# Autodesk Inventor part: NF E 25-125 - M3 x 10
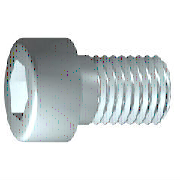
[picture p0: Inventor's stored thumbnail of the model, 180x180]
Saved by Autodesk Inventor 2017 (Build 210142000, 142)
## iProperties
Comments: To add or edit properties for Autodesk Inventor files, use iProperties.
Created: 2004-01
Part Number: NF E 25-125 - M3 x 10
Vendor: Autodesk Inc.
Document SubType Name: Modeling
Designer: Administrator
Material: Generic
Description: Cylinder Head Cap Screw
Standard: NF E 25-125
Size Designation: M3 x 10
Density: 1 g/cm^3
Appearance: Default
Alert: To add or edit properties for Autodesk Inventor files, use iProperties.
Control State: 0
Master: False
Checked Out: False
Shininess: 64.0
Length Units: 11269
Angle Units: 11279
Time Units: 11290
Mass Units: 11283
Length Display Precision: 3
Angle Display Precision: 2
Compacted: True
EGR: 1
Density: 0.0
Volumn: 0.0
Area: 0.0
PropertySet Name: Model Information
Author: Administrator
Revision Number: 8
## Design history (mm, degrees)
sketch "Sketch1"
  geometry: L1 (-0.867, 0)-(10, 0); L2 (10, 0)-(10, 1.5); L3 (10, 1.5)-(1.25, 1.5); L4 (1.25, 1.5)-(0.943, 1.5); L5 (0.943, 1.5)-(0, 1.5); L6 (0, 1.5)-(0, 2.75); L7 (0, 2.75)-(-3, 2.75); L8 (-3, 2.75)-(-3, 1.443); L9 (-3, 1.443)-(-1.7, 1.443); L10 (-1.7, 1.443)-(-0.867, 0); L11 (-4.3, 0)-(13.9, 0) reference; L12 (0, -0.275)-(0, 3.575) reference; L13 (1.25, 1.5)-(0, 1.5)
  constraints: 22 end point, 6 parallel, 2 collinear, 2 perpendicular, 1 horizontal, 1 point on line
  dimensions: "d1" = 8.75 distance from line of L3.end L2 (= GEL); "d2" = 0.30683 distance of L4.end L3.end (computed from GAL); "d3" = 3 distance between parallel lines of L8 L6 (= KOH); "d4" = 1.3 distance of L8.end L9.end (= INTI); "d5" = 60 deg angle of L10 L1; "d6" = 3 diameter of L3 L1 (= GD); "d7" = 3 diameter of L5 L1 (= BDM); "d8" = 2.88675 diameter of L9 L1 (= 1.1547 x SW); "d9" = 5.5 diameter of L7 L1 (= KOD); "d26" = 10 distance between parallel lines of L12 L2 (= NLG)
revolve "Body" sketch "Sketch1" stored, may be unused: angle "d10" = 90 deg
sketch "Sketch2"
  geometry: L1 (0, -3.3)-(0, 4.4) reference; L2 (-3.3, 0)-(4.4, 0) reference; L3 (1.443, 0)-(0.722, -1.25); L4 (0.722, -1.25)-(-0.722, -1.25); L5 (-0.722, -1.25)-(-1.443, 0); L6 (-1.443, 0)-(-0.722, 1.25); L7 (-0.722, 1.25)-(0.722, 1.25); L8 (0.722, 1.25)-(1.443, 0); 2 further points
  constraints: 12 end point, 1 coincident, 1 horizontal alignment, 1 point on line, 12 other
extrude "Slot" join sketch "Sketch2" stored distance "d11" = 10; taper "d12" = 0 deg
body "Solid1"
fillet "Fillet1" dims "d17" = 0.3 (= RR)
feature "Thread" dims "d13" = 8.75 (= GEL), "d14" = 0
chamfer "Chamfer1" distance "d15" = 0.30673 (= -0.5 x SPD + 0.5 x GD); stored, may be unused: second distance "d16" = 0.30673 (= GUL), angle "d27" = 45 deg
other parameters: "GD" = 3 (= NND) [user parameter; used in 2 equation terms], "NLG" = 10 [user parameter; used in 1 equation term], "GEL" = 8.75 [user parameter; used in 2 equation terms], "KOD" = 5.5 [user parameter; used in 1 equation term], "KOH" = 3 (= NND) [user parameter; used in 1 equation term], "INTI" = 1.3 [user parameter; used in 1 equation term], "GAL" = 0.30673 (= 0.61345 x TPU) [user parameter; used in 1 equation term], "GUL" = 0.30673 (= 0.61345 x TPU) [user parameter; used in 1 equation term], "BDM" = 3 (= NND) [user parameter; used in 1 equation term], "SW" = 2.5 [user parameter; used in 2 equation terms], "RR" = 0.3 [user parameter; used in 1 equation term], "SPD" = 2.38655 (= NND - 1.2269 x TPU) [user parameter; used in 1 equation term], "d18" = 0, "d19" = 0, "NND" = 3 [user parameter; used in 4 equation terms], "E0" = 2.8875 (= 1.155 x SW) [user parameter], "FAWI" = 45 deg [user parameter], "THREADDIA" = 3 [user parameter; used in 1 equation term], "TPU" = 0.5 [user parameter; used in 5 equation terms], "GD1" = 2.38655 (= THREADDIA - 1.2269 x TPU) [user parameter], "PTC" = 0.5 (= TPU) [user parameter], "TOA" = 30 deg [user parameter]
